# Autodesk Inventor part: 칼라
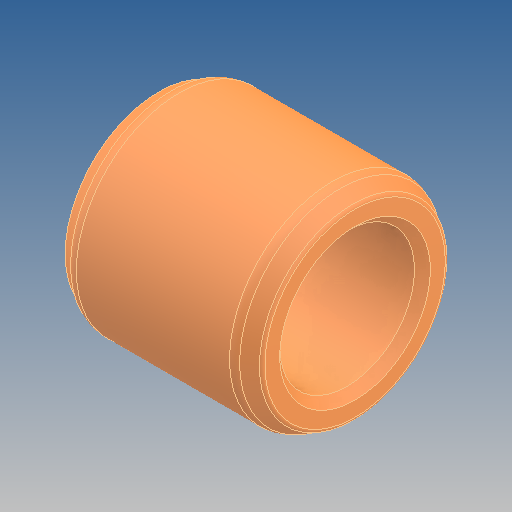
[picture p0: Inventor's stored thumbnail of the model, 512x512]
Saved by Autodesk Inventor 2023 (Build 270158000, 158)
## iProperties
Created: 2025-03
Part Number: 칼라
Material: 강철, 연강
Document SubType Name: Modeling
Designer: Admin
Density: 7.86 g/cm^3
Appearance: 기본값
Author: jhkim
Sending System: Autodesk Inventor 2025
Preprocessor: ST-DEVELOPER v20
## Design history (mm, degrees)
node "칼라1"
node "솔리드2"
node "솔리드1"
